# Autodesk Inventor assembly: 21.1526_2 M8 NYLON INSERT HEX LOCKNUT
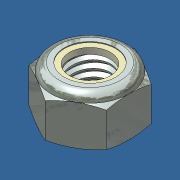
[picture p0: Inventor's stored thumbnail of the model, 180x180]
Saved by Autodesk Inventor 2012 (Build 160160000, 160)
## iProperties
Created: 2014-10
Part Number: 21.1526_2 M8 NYLON INSERT HEX LOCKNUT
Document SubType Name: Assembly
Designer: Admin
Mass: 5.53953 g
Surface Area: 11.368 cm^2
Volume: 0.773702 cm^3
Density: 7.15976 g/cm^3
Translation Standard: STEP AP203
FileName: 94645A210.step
PreProcessor: SolidWorks 2007
PostProcessor: Build: 160, Release: 2012 RTM - Date: Tue 03/01/2011
Sent Units: millimeter
Uncertainty: 1e-05
Author: Admin
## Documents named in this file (3)
- C:\Andys Backup Data\ANDY'S INVENTOR\INVENTOR LIBRARIES\PARTS LIBRARY\FASTENING ELEMENTS\NUTS\21.1526_2 M8 NYLON INSERT HEX LOCKNUT.iam
- C:\Andys Backup Data\ANDY'S INVENTOR\INVENTOR LIBRARIES\PARTS LIBRARY\FASTENING ELEMENTS\NUTS\SUBCOMPONENTS\21.1526_2 M8 HEX LOCKNUT STEEL NUT.ipt
- C:\Andys Backup Data\ANDY'S INVENTOR\INVENTOR LIBRARIES\PARTS LIBRARY\FASTENING ELEMENTS\NUTS\SUBCOMPONENTS\21.1526_2 M8 HEX LOCKNUT NYLON INSERT.ipt
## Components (2 placed, 2 different names)
1. 21.1526_2 M8 HEX LOCKNUT STEEL NUT:1 — Flush:1, Mate:1
2. 21.1526_2 M8 HEX LOCKNUT NYLON INSERT:1 — Flush:1, Mate:1
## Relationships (2: Flush 1, Mate 1)
- Flush:1: 21.1526_2 M8 HEX LOCKNUT STEEL NUT:1 ↔ 21.1526_2 M8 HEX LOCKNUT NYLON INSERT:1
- Mate:1: 21.1526_2 M8 HEX LOCKNUT STEEL NUT:1 ↔ 21.1526_2 M8 HEX LOCKNUT NYLON INSERT:1
